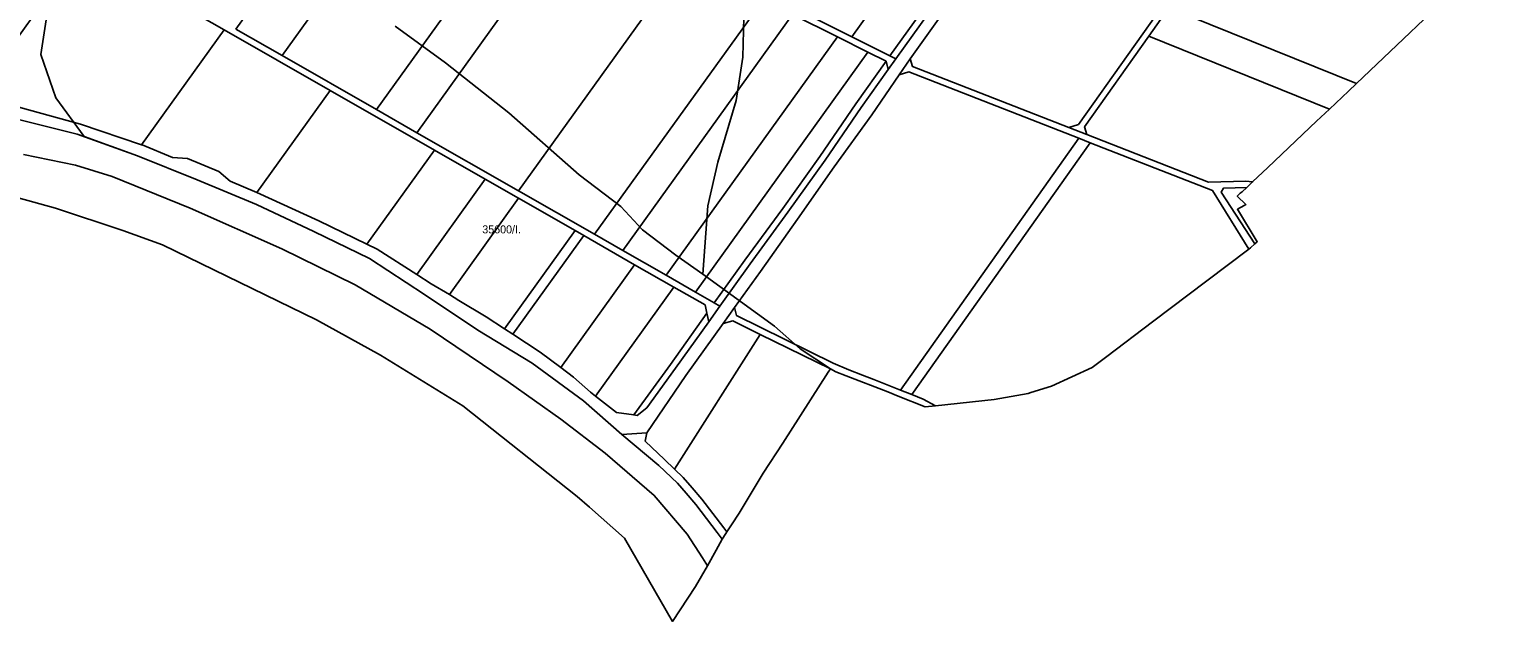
# Model space of a CAD drawing. Extents: x -545779 to -541342, y -1153413 to -1149956.
# Drawn here: x -542328 to -541406, y -1151576 to -1151207 of the extents above; entities that cross this region are included whole.
import ezdxf

# ---------------------------------------------------------------- set-up
doc = ezdxf.new("R2010")
doc.units = 0
for name, color, linetype in [('95560013', 7, 'Continuous'), ('95630013', 7, 'Continuous'), ('95640013', 7, 'Continuous'), ('95660013', 7, 'Continuous')]:
    doc.layers.add(name, color=color, linetype=linetype)

msp = doc.modelspace()

# ---------------------------------------------------------------- linework, layer by layer
at = {"layer": '95560013'}
for points in [[(-541687.38, -1151034.5), (-541750.87, -1151122.91), (-541814.34, -1151211.29), (-541837.58, -1151199.67), (-541774.21, -1151111.43), (-541710.82, -1151023.16)], [(-541669.73, -1151051.8), (-541736.32, -1151147.65), (-541790.54, -1151223.2), (-541814.34, -1151211.29), (-541750.87, -1151122.91), (-541687.38, -1151034.5), (-541677.17, -1151039.39), (-541676.61, -1151039.66), (-541669.27, -1151043.18)], [(-542199.09, -1151206.46), (-542102.3, -1151071.67), (-542072.32, -1151086.67), (-542170.21, -1151222.98)], [(-542111.19, -1151256.73), (-542170.21, -1151222.98), (-542072.32, -1151086.67), (-542011.07, -1151117.32)], [(-541405.91, -1151152.25), (-541444.34, -1151188.63), (-541482.08, -1151224.37), (-541499.04, -1151240.43), (-541616.16, -1151193.07), (-541546.92, -1151095.23), (-541494.83, -1151117.22), (-541420.73, -1151146.35)], [(-542086.03, -1151271.12), (-542111.19, -1151256.73), (-542011.07, -1151117.32), (-541984.96, -1151130.39)], [(-542086.03, -1151271.12), (-541984.96, -1151130.39), (-541918.97, -1151163.41), (-542022.44, -1151307.48)], [(-541678.76, -1151267.88), (-541776.35, -1151229.77), (-541777.76, -1151225.04), (-541756.04, -1151194.31), (-541734.18, -1151160.78), (-541714.29, -1151134.76), (-541610.68, -1151178.39), (-541672.73, -1151266.07)], [(-542334.58, -1151255.2), (-542362.09, -1151248.73), (-542295.47, -1151155.96), (-542206.42, -1151206.88), (-542257.96, -1151278.65), (-542295.99, -1151265.81)], [(-541918.97, -1151163.41), (-541869.73, -1151188.05), (-541974.99, -1151334.62), (-542022.44, -1151307.48)], [(-541957.25, -1151344.77), (-541974.99, -1151334.62), (-541869.73, -1151188.05), (-541851.32, -1151197.26)], [(-541957.25, -1151344.77), (-541851.32, -1151197.26), (-541823.27, -1151211.3), (-541930.22, -1151360.23)], [(-541515.91, -1151256.41), (-541628.71, -1151210.8), (-541616.16, -1151193.07), (-541499.04, -1151240.43), (-541504.06, -1151245.18)], [(-542257.64, -1151278.76), (-542257.96, -1151278.65), (-542206.42, -1151206.88), (-542140.17, -1151244.77), (-542185.87, -1151308.4), (-542202.53, -1151301.51), (-542209.71, -1151295.3), (-542229.24, -1151287.23), (-542238.72, -1151286.57)], [(-541911.88, -1151370.71), (-541930.22, -1151360.23), (-541823.27, -1151211.3), (-541804.23, -1151220.82)], [(-541554.44, -1151292.89), (-541563.88, -1151301.83), (-541568.04, -1151301.35), (-541591.36, -1151302.02), (-541667.47, -1151272.29), (-541668.89, -1151267.57), (-541628.71, -1151210.8), (-541515.91, -1151256.41), (-541523.92, -1151263.99)], [(-541857.42, -1151318.5), (-541881.08, -1151350.75), (-541900.14, -1151377.42), (-541911.88, -1151370.71), (-541804.23, -1151220.82), (-541792.84, -1151226.52), (-541811.66, -1151253.06), (-541834.2, -1151286.01)], [(-541816.18, -1151419.31), (-541825.87, -1151415.02), (-541886.23, -1151385.38), (-541887.49, -1151380.36), (-541871.34, -1151357.75), (-541848.08, -1151325.21), (-541825.23, -1151292.37), (-541801.79, -1151259.87), (-541784.65, -1151234.99), (-541778.66, -1151233.16), (-541672.53, -1151274.6), (-541783.82, -1151431.92), (-541800.46, -1151425.41), (-541807.58, -1151422.64)], [(-542117.23, -1151340.78), (-542147.18, -1151326.15), (-542185.87, -1151308.4), (-542140.17, -1151244.77), (-542075.03, -1151282.02)], [(-542117.23, -1151340.78), (-542075.03, -1151282.02), (-542043.21, -1151300.22), (-542085.96, -1151359.75), (-542110.8, -1151343.92)], [(-541665.43, -1151277.38), (-541776.74, -1151434.73), (-541783.82, -1151431.92), (-541672.53, -1151274.6)], [(-541665.43, -1151277.38), (-541588.91, -1151307.29), (-541566.33, -1151343.84), (-541592.42, -1151363.73), (-541626.35, -1151389.27), (-541654.93, -1151410.97), (-541664.04, -1151417.75), (-541689.44, -1151429.54), (-541702.37, -1151433.43), (-541704.18, -1151433.97), (-541725.25, -1151437.72), (-541761.92, -1151441.67), (-541769.67, -1151437.53), (-541776.74, -1151434.73)], [(-542065.61, -1151372.29), (-542076.98, -1151365.47), (-542085.96, -1151359.75), (-542043.21, -1151300.22), (-542022.4, -1151312.12)], [(-542042.69, -1151386.07), (-542059.67, -1151375.86), (-542065.61, -1151372.29), (-542022.4, -1151312.12), (-541987.09, -1151332.32), (-542031.13, -1151393.64)], [(-541987.09, -1151332.32), (-541981.71, -1151335.41), (-542025.97, -1151397.03), (-542031.13, -1151393.64)], [(-542009, -1151408.15), (-542025.97, -1151397.03), (-541981.71, -1151335.41), (-541949.92, -1151353.58), (-541996.09, -1151417.86)], [(-541996.09, -1151417.86), (-541949.92, -1151353.58), (-541925.42, -1151367.59), (-541974.31, -1151435.66), (-541977.44, -1151433.21), (-541988.12, -1151423.85)], [(-541925.42, -1151367.59), (-541905.96, -1151378.72), (-541904.81, -1151383.96), (-541927.61, -1151415.85), (-541950.44, -1151447.49), (-541961.19, -1151445.94), (-541974.31, -1151435.66)], [(-541917.85, -1151422.84), (-541894.59, -1151390.3), (-541888.57, -1151388.66), (-541871.43, -1151397.1), (-541924.98, -1151481.4), (-541931.29, -1151475.37), (-541943.26, -1151463.92), (-541942.36, -1151458.56)], [(-541884.69, -1151508.78), (-541889.39, -1151516.15), (-541892.29, -1151520.45), (-541894.23, -1151517.91), (-541907.86, -1151500.16), (-541914, -1151493.03), (-541919.53, -1151486.6), (-541924.98, -1151481.4), (-541871.43, -1151397.1), (-541827.61, -1151418.62), (-541828.93, -1151420.69), (-541857.45, -1151465.1), (-541869.63, -1151483.93)]]:
    msp.add_lwpolyline(points, close=True, dxfattribs=at)
at = {"layer": '95630013'}
msp.add_lwpolyline([(-541715.58, -1151124.94), (-541738.26, -1151157.89), (-541761.76, -1151190.27), (-541786.85, -1151224.91), (-541790.54, -1151223.2), (-541736.32, -1151147.65), (-541669.73, -1151051.8), (-541669.99, -1151056.64), (-541670.97, -1151059.35), (-541676.45, -1151069.39), (-541692.5, -1151092.27)], close=True, dxfattribs=at)
msp.add_lwpolyline([(-542331.67, -1151284.76), (-542299.23, -1151291.36), (-542276.39, -1151298.44), (-542227.52, -1151318.28), (-542170.24, -1151343.71), (-542124.52, -1151366.15), (-542077.75, -1151393.85), (-542028.95, -1151426.86), (-541996.12, -1151450.12), (-541968.36, -1151471.37), (-541937.64, -1151497.73), (-541917.14, -1151522.01), (-541907.62, -1151536.71), (-541904.34, -1151541.77), (-541911.83, -1151554.71), (-541926.26, -1151576.49), (-541956.17, -1151524.36), (-541978.14, -1151505.15), (-541985.8, -1151498.46), (-542057.28, -1151441.71), (-542108.58, -1151410.14), (-542148.68, -1151388.03), (-542244.89, -1151341.18), (-542269.57, -1151332.27), (-542311.73, -1151318.19), (-542358.55, -1151305.44)], dxfattribs=at)
at = {"layer": '95640013'}
for points in [[(-541610.68, -1151178.39), (-541600.23, -1151163.63), (-541589.71, -1151148.76), (-541577.13, -1151131), (-541550.69, -1151093.64), (-541546.92, -1151095.23), (-541616.16, -1151193.07), (-541628.71, -1151210.8), (-541668.89, -1151267.57), (-541667.47, -1151272.29), (-541678.76, -1151267.88), (-541672.73, -1151266.07)], [(-541881.08, -1151350.75), (-541857.42, -1151318.5), (-541834.2, -1151286.01), (-541811.66, -1151253.06), (-541792.84, -1151226.52), (-541791.57, -1151231.58), (-541808.38, -1151255.34), (-541830.92, -1151288.3), (-541854.18, -1151320.85), (-541877.84, -1151353.1), (-541896.65, -1151379.42), (-541900.14, -1151377.42)], [(-541591.36, -1151302.02), (-541568.04, -1151301.35), (-541563.88, -1151301.83), (-541567.57, -1151305.32), (-541582.01, -1151305.76), (-541583.6, -1151308.28), (-541562.48, -1151340.58), (-541565.25, -1151343.02), (-541566.33, -1151343.84), (-541588.91, -1151307.29), (-541665.43, -1151277.38), (-541672.53, -1151274.6), (-541778.66, -1151233.16), (-541784.65, -1151234.99), (-541777.76, -1151225.04), (-541776.35, -1151229.77), (-541678.76, -1151267.88), (-541667.47, -1151272.29)], [(-541573.4, -1151319), (-541560.96, -1151339.24), (-541562.48, -1151340.58), (-541583.6, -1151308.28), (-541582.01, -1151305.76), (-541567.57, -1151305.32), (-541570.4, -1151308), (-541571.56, -1151308.9), (-541573.46, -1151310.88), (-541568.08, -1151315.96), (-541569.18, -1151316.59)], [(-541904.81, -1151383.96), (-541903.66, -1151389.23), (-541924.36, -1151418.19), (-541942.23, -1151442.95), (-541948.26, -1151447.8), (-541950.44, -1151447.49), (-541927.61, -1151415.85)], [(-541761.92, -1151441.67), (-541768.33, -1151442.36), (-541785.23, -1151435.66), (-541791.85, -1151433.04), (-541817.7, -1151423.01), (-541824.24, -1151420.44), (-541827.61, -1151418.62), (-541871.43, -1151397.1), (-541888.57, -1151388.66), (-541894.59, -1151390.3), (-541887.49, -1151380.36), (-541886.23, -1151385.38), (-541825.87, -1151415.02), (-541816.18, -1151419.31), (-541807.58, -1151422.64), (-541800.46, -1151425.41), (-541783.82, -1151431.92), (-541776.74, -1151434.73), (-541769.67, -1151437.53)], [(-541895.31, -1151525.14), (-541898.27, -1151520.86), (-541911.74, -1151503.32), (-541917.79, -1151496.29), (-541923.16, -1151490.05), (-541934.74, -1151478.98), (-541957.83, -1151459.78), (-541942.36, -1151458.56), (-541943.26, -1151463.92), (-541931.29, -1151475.37), (-541924.98, -1151481.4), (-541919.53, -1151486.6), (-541914, -1151493.03), (-541907.86, -1151500.16), (-541894.23, -1151517.91), (-541892.29, -1151520.45), (-541892.98, -1151521.47)]]:
    msp.add_lwpolyline(points, close=True, dxfattribs=at)
for points in [[(-542199.09, -1151206.46), (-542170.21, -1151222.98), (-542111.19, -1151256.73), (-542086.03, -1151271.12), (-542022.44, -1151307.48), (-541974.99, -1151334.62), (-541957.25, -1151344.77), (-541930.22, -1151360.23), (-541911.88, -1151370.71), (-541900.14, -1151377.42), (-541896.65, -1151379.42), (-541903.66, -1151389.23), (-541904.81, -1151383.96), (-541905.96, -1151378.72), (-541925.42, -1151367.59), (-541949.92, -1151353.58), (-541981.71, -1151335.41), (-541987.09, -1151332.32), (-542022.4, -1151312.12), (-542043.21, -1151300.22), (-542075.03, -1151282.02), (-542140.17, -1151244.77), (-542206.42, -1151206.88), (-542295.47, -1151155.96)], [(-542334.58, -1151255.2), (-542295.99, -1151265.81), (-542257.96, -1151278.65), (-542257.64, -1151278.76), (-542238.72, -1151286.57), (-542229.24, -1151287.23), (-542209.71, -1151295.3), (-542202.53, -1151301.51), (-542185.87, -1151308.4), (-542147.18, -1151326.15), (-542117.23, -1151340.78), (-542110.8, -1151343.92), (-542085.96, -1151359.75), (-542076.98, -1151365.47), (-542065.61, -1151372.29), (-542059.67, -1151375.86), (-542042.69, -1151386.07), (-542031.13, -1151393.64), (-542025.97, -1151397.03), (-542009, -1151408.15), (-541996.09, -1151417.86), (-541988.12, -1151423.85), (-541977.44, -1151433.21), (-541974.31, -1151435.66), (-541961.19, -1151445.94), (-541950.44, -1151447.49), (-541948.26, -1151447.8), (-541942.23, -1151442.95), (-541924.36, -1151418.19), (-541903.66, -1151389.23), (-541896.65, -1151379.42), (-541877.84, -1151353.1), (-541854.18, -1151320.85), (-541830.92, -1151288.3), (-541808.38, -1151255.34), (-541791.57, -1151231.58), (-541786.85, -1151224.91), (-541761.76, -1151190.27)], [(-541756.04, -1151194.31), (-541777.76, -1151225.04), (-541784.65, -1151234.99), (-541801.79, -1151259.87), (-541825.23, -1151292.37), (-541848.08, -1151325.21), (-541871.34, -1151357.75), (-541887.49, -1151380.36), (-541894.59, -1151390.3), (-541917.85, -1151422.84), (-541942.36, -1151458.56), (-541957.83, -1151459.78), (-541981.87, -1151438.63), (-542013.91, -1151415.08), (-542047.95, -1151394.57), (-542081.19, -1151372.27), (-542115.64, -1151349.77), (-542150.34, -1151332.95), (-542186.05, -1151315.9), (-542223.21, -1151300.54), (-542260.39, -1151285.52), (-542298.1, -1151271.97), (-542336.56, -1151262.44)], [(-541837.58, -1151199.67), (-541814.34, -1151211.29), (-541790.54, -1151223.2), (-541786.85, -1151224.91), (-541791.57, -1151231.58), (-541792.84, -1151226.52), (-541804.23, -1151220.82), (-541823.27, -1151211.3), (-541851.32, -1151197.26)], [(-542336.56, -1151262.44), (-542298.1, -1151271.97), (-542260.39, -1151285.52), (-542223.21, -1151300.54), (-542186.05, -1151315.9), (-542150.34, -1151332.95), (-542115.64, -1151349.77), (-542081.19, -1151372.27), (-542047.95, -1151394.57), (-542013.91, -1151415.08), (-541981.87, -1151438.63), (-541957.83, -1151459.78), (-541934.74, -1151478.98), (-541923.16, -1151490.05), (-541917.79, -1151496.29), (-541911.74, -1151503.32), (-541898.27, -1151520.86), (-541895.31, -1151525.14), (-541898.94, -1151531.84), (-541904.34, -1151541.77), (-541907.62, -1151536.71), (-541917.14, -1151522.01), (-541937.64, -1151497.73), (-541968.36, -1151471.37), (-541996.12, -1151450.12), (-542028.95, -1151426.86), (-542077.75, -1151393.85), (-542124.52, -1151366.15), (-542170.24, -1151343.71), (-542227.52, -1151318.28), (-542276.39, -1151298.44), (-542299.23, -1151291.36), (-542331.67, -1151284.76)]]:
    msp.add_lwpolyline(points, dxfattribs=at)
at = {"layer": '95660013'}
for points in [[(-541881.292, -1151182.081), (-541882.335, -1151223.84), (-541886.511, -1151250.983), (-541897.996, -1151289.61), (-541904.259, -1151316.753), (-541907.392, -1151359.556), (-541924.094, -1151347.55), (-541944.974, -1151331.891), (-541958.546, -1151317.275), (-541984.645, -1151297.44), (-542028.493, -1151258.813), (-542068.164, -1151227.494), (-542099.482, -1151204.526)], [(-541444.34, -1151188.63), (-541482.08, -1151224.37), (-541499.04, -1151240.43), (-541504.06, -1151245.18), (-541515.91, -1151256.41), (-541523.92, -1151263.99), (-541554.44, -1151292.89), (-541563.88, -1151301.83), (-541567.57, -1151305.32), (-541570.4, -1151308), (-541571.56, -1151308.9), (-541573.46, -1151310.88), (-541568.08, -1151315.96), (-541569.18, -1151316.59), (-541573.4, -1151319), (-541560.96, -1151339.24), (-541562.48, -1151340.58), (-541565.25, -1151343.02), (-541566.33, -1151343.84), (-541592.42, -1151363.73), (-541626.35, -1151389.27), (-541654.93, -1151410.97), (-541664.04, -1151417.75), (-541689.44, -1151429.54), (-541702.37, -1151433.43), (-541704.18, -1151433.97), (-541725.25, -1151437.72), (-541761.92, -1151441.67), (-541768.33, -1151442.36), (-541785.23, -1151435.66), (-541791.85, -1151433.04), (-541817.7, -1151423.01), (-541824.24, -1151420.44), (-541827.61, -1151418.62), (-541846.539, -1151406.204), (-541862.594, -1151392.073), (-541907.392, -1151359.556), (-541904.259, -1151316.753), (-541897.996, -1151289.61), (-541886.511, -1151250.983), (-541882.335, -1151223.84), (-541881.292, -1151182.081)], [(-542316.629, -1151195.131), (-542320.805, -1151222.274), (-542311.408, -1151249.417), (-542293.714, -1151273.546), (-542298.1, -1151271.97), (-542336.56, -1151262.44)], [(-542099.482, -1151204.526), (-542068.164, -1151227.494), (-542028.493, -1151258.813), (-541984.645, -1151297.44), (-541958.546, -1151317.275), (-541944.974, -1151331.891), (-541924.094, -1151347.55), (-541907.392, -1151359.556), (-541862.594, -1151392.073), (-541846.539, -1151406.204), (-541827.61, -1151418.62), (-541828.93, -1151420.69), (-541857.45, -1151465.1), (-541869.63, -1151483.93), (-541884.69, -1151508.78), (-541889.39, -1151516.15), (-541892.29, -1151520.45), (-541892.98, -1151521.47), (-541895.31, -1151525.14), (-541898.27, -1151520.86), (-541911.74, -1151503.32), (-541917.79, -1151496.29), (-541923.16, -1151490.05), (-541934.74, -1151478.98), (-541957.83, -1151459.78), (-541981.87, -1151438.63), (-542013.91, -1151415.08), (-542047.95, -1151394.57), (-542081.19, -1151372.27), (-542115.64, -1151349.77), (-542150.34, -1151332.95), (-542186.05, -1151315.9), (-542223.21, -1151300.54), (-542260.39, -1151285.52), (-542293.714, -1151273.546), (-542311.408, -1151249.417), (-542320.805, -1151222.274), (-542316.629, -1151195.131)], [(-542336.56, -1151262.44), (-542298.1, -1151271.97), (-542293.714, -1151273.546), (-542260.39, -1151285.52), (-542223.21, -1151300.54), (-542186.05, -1151315.9), (-542150.34, -1151332.95), (-542115.64, -1151349.77), (-542081.19, -1151372.27), (-542047.95, -1151394.57), (-542013.91, -1151415.08), (-541981.87, -1151438.63), (-541957.83, -1151459.78), (-541934.74, -1151478.98), (-541923.16, -1151490.05), (-541917.79, -1151496.29), (-541911.74, -1151503.32), (-541898.27, -1151520.86), (-541895.31, -1151525.14), (-541898.94, -1151531.84), (-541904.34, -1151541.77), (-541911.83, -1151554.71), (-541926.26, -1151576.49), (-541956.17, -1151524.36), (-541978.14, -1151505.15), (-541985.8, -1151498.46), (-542057.28, -1151441.71), (-542108.58, -1151410.14), (-542148.68, -1151388.03), (-542244.89, -1151341.18), (-542269.57, -1151332.27), (-542311.73, -1151318.19), (-542358.55, -1151305.44)]]:
    msp.add_lwpolyline(points, dxfattribs=at)

# ---------------------------------------------------------------- texts
msp.add_text('35600/I.', height=5, rotation=360, dxfattribs=at).set_placement((-542045.107, -1151334.036))

doc.saveas('drawing.dxf')
